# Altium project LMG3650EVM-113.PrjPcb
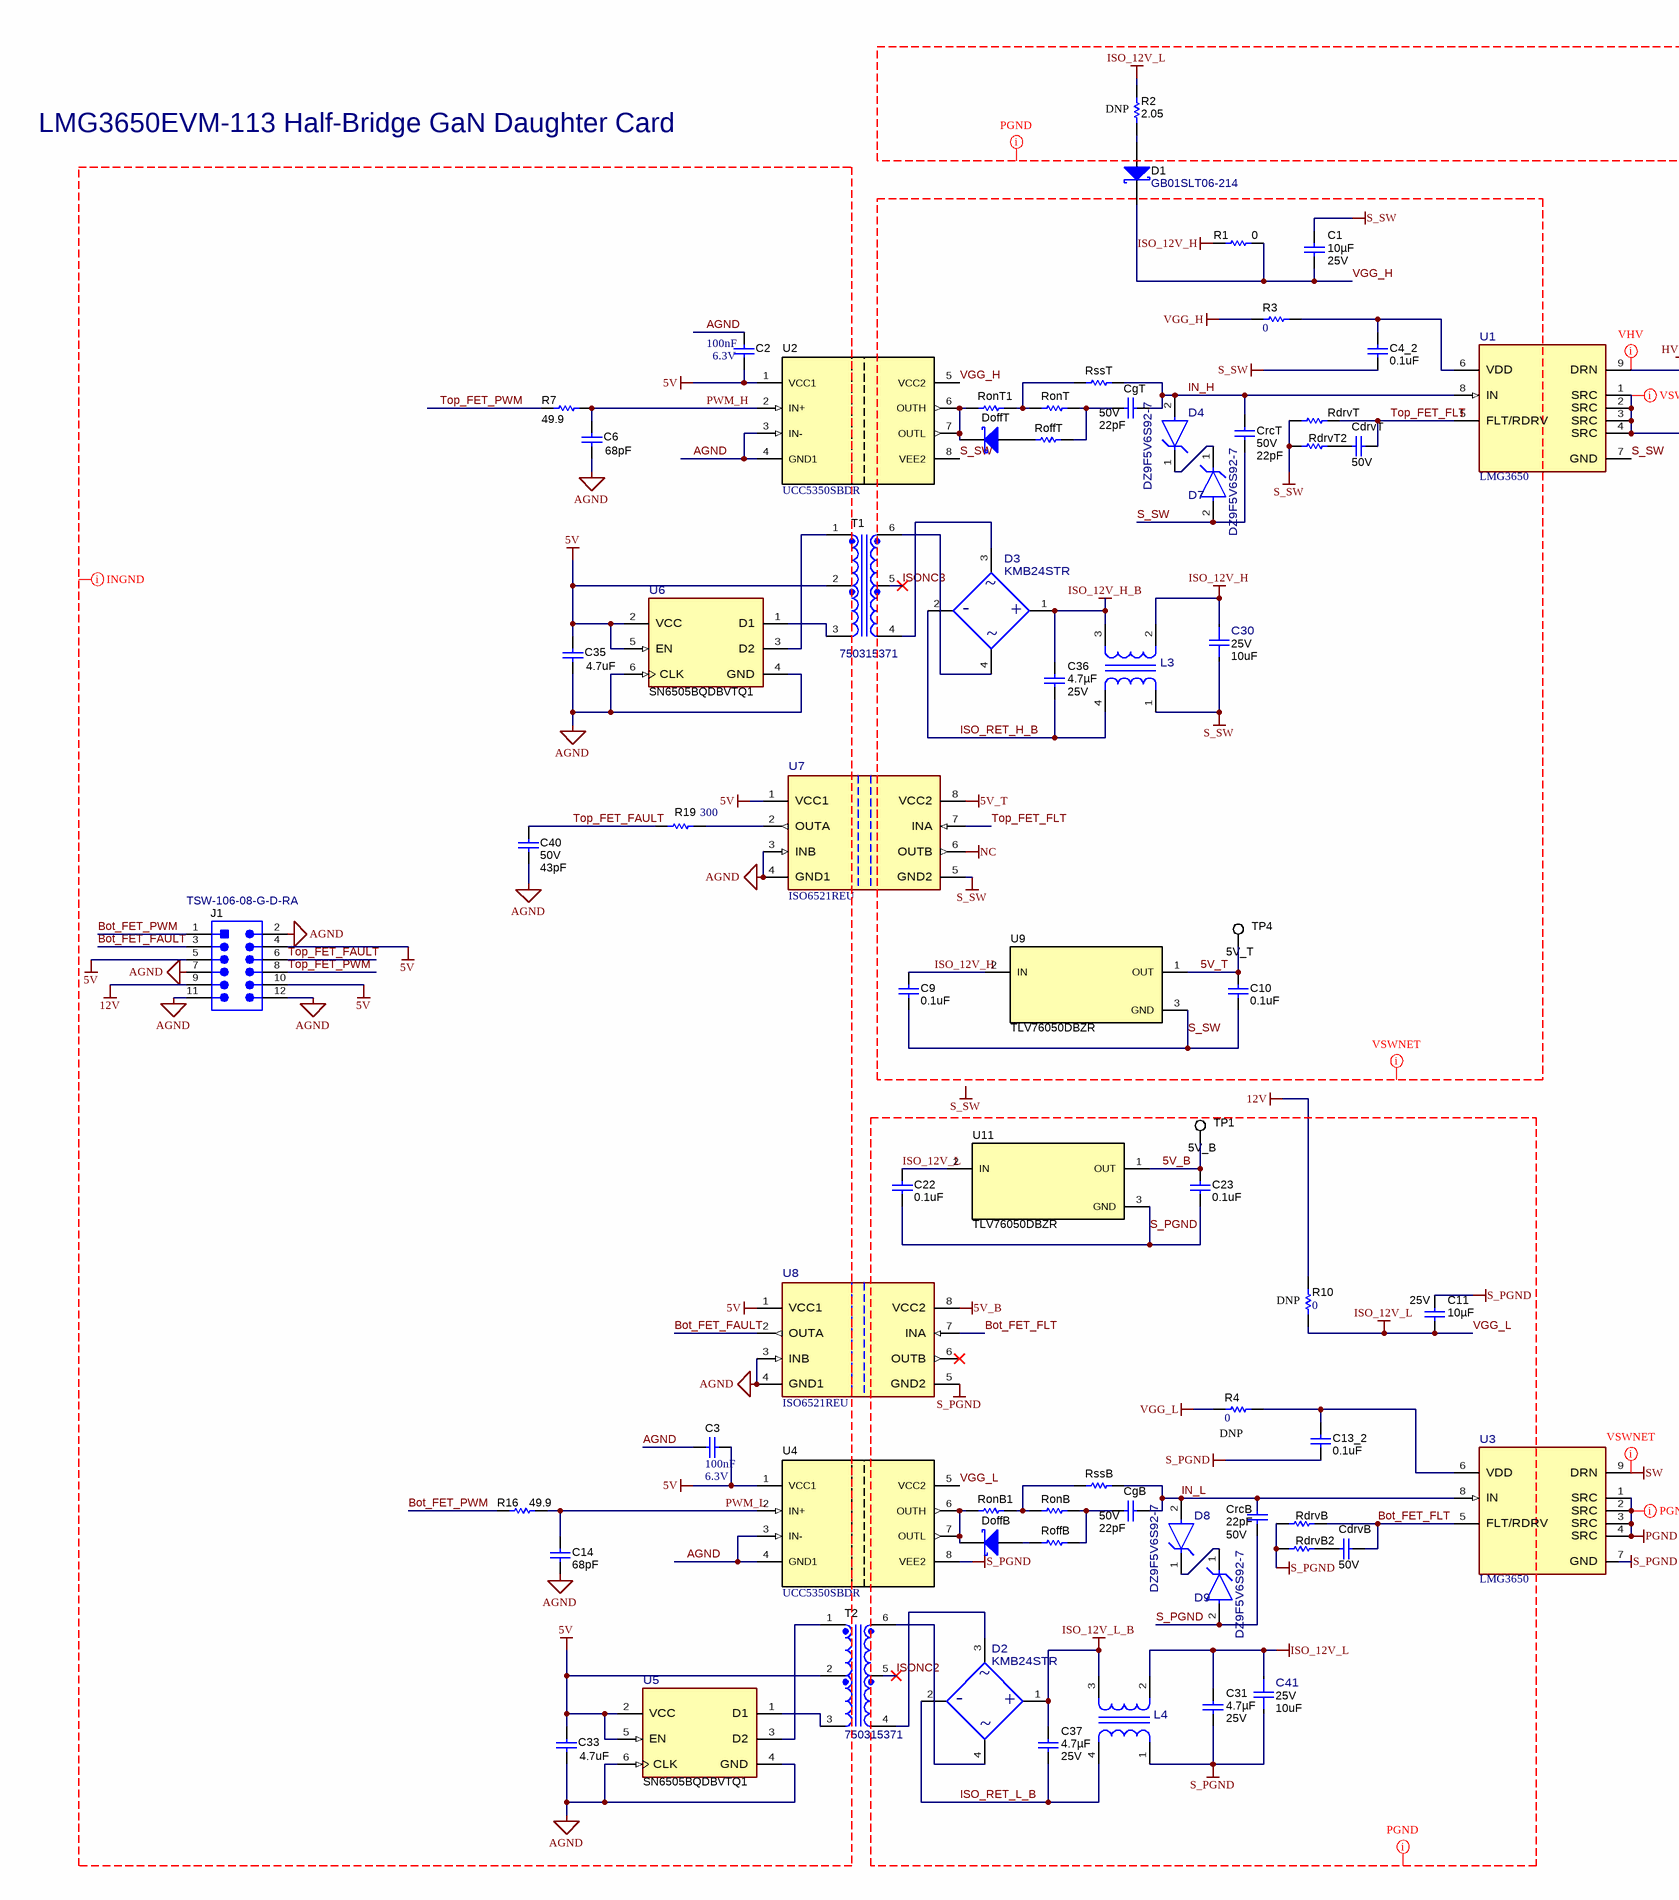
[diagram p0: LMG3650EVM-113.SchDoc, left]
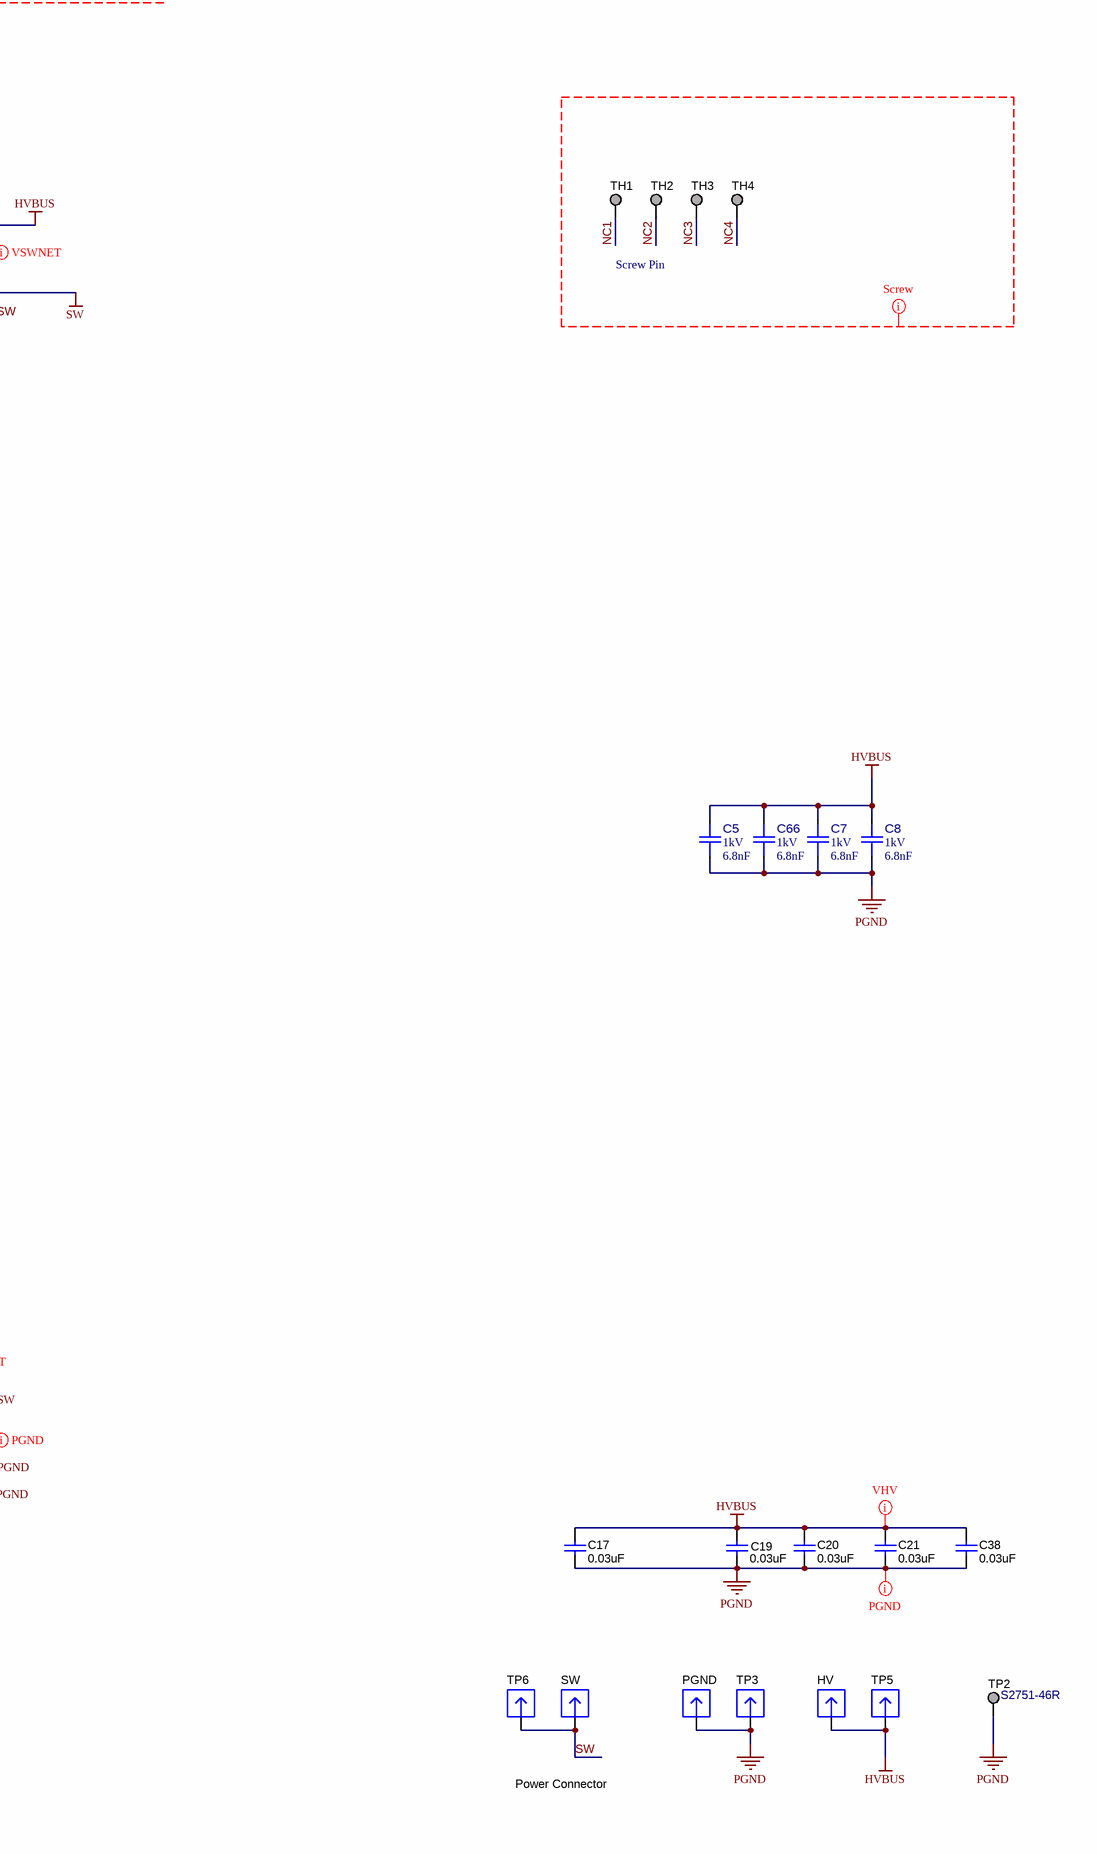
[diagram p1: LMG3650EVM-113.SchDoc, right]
CopyrightYear: 2020; Drawnby: Kyle Wolf; PCB_Layout: Kyle Wolf; PCB_Rev: A1; PRJ_Customer: Public Release; PRJ_Engineer: Kyle Wolf; PRJ_Number: HVP113; PRJ_Title: Sunliner; SCH_Rev: A1; TechSupport: http://www.ti.com/support; TID: N/A
2 sheets, 108 parts. Net scope: global (net labels, ports and power ports of the same name join across sheets).
Board file: LMG3650EVM-113.PcbDoc
Sheets:
  LMG3650EVM-113.SchDoc
  LMG3650EVM-113_Hardware.SchDoc

## Sheet LMG3650EVM-113.SchDoc: Phase Leg
size A2; Date: Not shown in title block; ApprovedBy: Not shown in title block; CheckedBy: Not shown in title block; Author: Not shown in title block; CompanyName: Not shown in title block; DrawnBy: Fei Yang; Engineer: Not shown in title block; Organization: Not shown in title block; Address1: Not shown in title block; Address2: Not shown in title block; Address3: Not shown in title block; Address4: Not shown in title block; DocumentNumber: 2; Revision: Use project parameter SCH_Rev; SheetNumber: 2; SheetTotal: 3; PageSetup: Record=PageOptions¦CenterHorizontal=True¦CenterVertical=True¦PrintScale=1.00¦XCorrection=1.00¦YCorrection=1.00¦PrintKind=0¦BorderSize=5000000¦LeftOffset=0¦BottomOffset=0¦Orientation=2¦PaperLength=1000¦PaperWidth=1000¦Scale=100¦PaperSource=15¦PrintQuality=600¦MediaType=1¦DitherType=10¦PaperKind=Letter¦PrintScaleMode=1

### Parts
C1  VDC_V: 25V  ValueDisplayed: 10µF  [1206_180]  (hidden comment: TMK316AB7106KLHT)
C2  Cap_F: 100nF  VDC_V: 6.3V  [0603]  (hidden comment: GRM188R70J104KA01D)
C3  Cap_F: 100nF  VDC_V: 6.3V  [0603]  (hidden comment: GRM188R70J104KA01D)
C4_2  ValueDisplayed: 0.1uF  [0402]  (hidden comment: C1005X7R1H104K050BB)
C5  VDC_V: 1kV  ValueDisplayed: 6.8nF  [FP-CGA6M1C0G3A682J200AE_1210-MFG]  (hidden comment: CGA6M1C0G3A682J200AE)
C6  ValueDisplayed: 68pF  [0402]  (hidden comment: C1005C0G1H680J050BA)
C7  VDC_V: 1kV  ValueDisplayed: 6.8nF  [FP-CGA6M1C0G3A682J200AE_1210-MFG]  (hidden comment: CGA6M1C0G3A682J200AE)
C8  VDC_V: 1kV  ValueDisplayed: 6.8nF  [FP-CGA6M1C0G3A682J200AE_1210-MFG]  (hidden comment: CGA6M1C0G3A682J200AE)
C9  ValueDisplayed: 0.1uF  [0402]  (hidden comment: C1005X7R1H104K050BB)
C10  ValueDisplayed: 0.1uF  [0402]  (hidden comment: C1005X7R1H104K050BB)
C11  VDC_V: 25V  ValueDisplayed: 10µF  [1206_180]  (hidden comment: TMK316AB7106KLHT)
C13_2  ValueDisplayed: 0.1uF  [0402]  (hidden comment: C1005X7R1H104K050BB)
C14  ValueDisplayed: 68pF  [0402]  (hidden comment: C1005C0G1H680J050BA)
C17  ValueDisplayed: 0.03uF  [1812_254]  (hidden comment: C1812C303KDGLCAUTO)
C19  ValueDisplayed: 0.03uF  [1812_254]  (hidden comment: C1812C303KDGLCAUTO)
C20  ValueDisplayed: 0.03uF  [1812_254]  (hidden comment: C1812C303KDGLCAUTO)
C21  ValueDisplayed: 0.03uF  [1812_254]  (hidden comment: C1812C303KDGLCAUTO)
C22  ValueDisplayed: 0.1uF  [0402]  (hidden comment: C1005X7R1H104K050BB)
C23  ValueDisplayed: 0.1uF  [0402]  (hidden comment: C1005X7R1H104K050BB)
C30  VDC_V: 25V  ValueDisplayed: 10uF  [FP-CGA4J1X7S1E106K125AC_0805-MFG]  (hidden comment: CGA4J1X7S1E106K125AC)
C31  ValueDisplayed: 4.7µF  VDC_V: 25V  [0603]  (hidden comment: GRT188C81E475KE13D)
C33  ValueDisplayed: 4.7uF  [0805_HV]  (hidden comment: GCM21BR71C475KA73L)
C35  ValueDisplayed: 4.7uF  [0805_HV]  (hidden comment: GCM21BR71C475KA73L)
C36  ValueDisplayed: 4.7µF  VDC_V: 25V  [0603]  (hidden comment: GRT188C81E475KE13D)
C37  ValueDisplayed: 4.7µF  VDC_V: 25V  [0603]  (hidden comment: GRT188C81E475KE13D)
C38  ValueDisplayed: 0.03uF  [1812_254]  (hidden comment: C1812C303KDGLCAUTO)
C40  VDC_V: 50V  ValueDisplayed: 43pF  [0402]  (hidden comment: GCQ1555C1H430JB01D)
C41  VDC_V: 25V  ValueDisplayed: 10uF  [FP-CGA4J1X7S1E106K125AC_0805-MFG]  (hidden comment: CGA4J1X7S1E106K125AC)
C66  VDC_V: 1kV  ValueDisplayed: 6.8nF  [FP-CGA6M1C0G3A682J200AE_1210-MFG]  (hidden comment: CGA6M1C0G3A682J200AE)
CdrvB  VDC_V: 50V  [0402]  (hidden comment: GCM1555C1H220JA16D)
CdrvT  VDC_V: 50V  [0402]  (hidden comment: GCM1555C1H220JA16D)
CgB  VDC_V: 50V  ValueDisplayed: 22pF  [0402]  (hidden comment: GCM1555C1H220JA16D (NC))
CgT  VDC_V: 50V  ValueDisplayed: 22pF  [0402]  (hidden comment: GCM1555C1H220JA16D (NC))
CrcB  VDC_V: 50V  ValueDisplayed: 22pF  [0402]  (hidden comment: GCM1555C1H220JA16D)
CrcT  VDC_V: 50V  ValueDisplayed: 22pF  [0402]  (hidden comment: GCM1555C1H220JA16D)
D1  GB01SLT06-214  [SMB]
D2  KMB24STR  [FP-KMB24STR_SMD4-MFG]
D3  KMB24STR  [FP-KMB24STR_SMD4-MFG]
D4  DZ9F5V6S92-7  [FP-CDZVT2R5.1B_SOD-923-MFG]
D7  DZ9F5V6S92-7  [FP-CDZVT2R5.1B_SOD-923-MFG]
D8  DZ9F5V6S92-7  [FP-CDZVT2R5.1B_SOD-923-MFG]
D9  DZ9F5V6S92-7  [FP-CDZVT2R5.1B_SOD-923-MFG]
DoffB  NSR05F30NXT5G  [DSN2_0402]  (value not drawn)
DoffT  NSR05F30NXT5G  [DSN2_0402]  (value not drawn)
HV  3621-0-32-15-00-00-08-0  [Mill-Max_3621-0-32-xx-00-00-08-0]  (value not drawn)
J1  TSW-106-08-G-D-RA  [AB12-DEST]
L3  ACM2012-900-2P-T001  [FP-ACM2012-900-2P-T001_SMD4-MFG]  (value not drawn)
L4  ACM2012-900-2P-T001  [FP-ACM2012-900-2P-T001_SMD4-MFG]  (value not drawn)
PGND  3621-0-32-15-00-00-08-0  [Mill-Max_3621-0-32-xx-00-00-08-0]  (value not drawn)
R1  ValueDisplayed: 0  [0805_HV]  (hidden comment: CRCW08050000Z0EAHP)
R2  ValueDisplayed: 2.05  [1206]  (hidden comment: CRCW12062R05FKEA)  (no BOM)
R3  ValueDisplayed: 0  [0603]  (hidden comment: CRCW06030000Z0EA)
R4  ValueDisplayed: 0  [0603]  (hidden comment: CRCW06030000Z0EA)
R7  ValueDisplayed: 49.9  [0402]  (hidden comment: CRCW040249R9FKED)
R10  ValueDisplayed: 0  [1206]  (hidden comment: ERJ-8GEY0R00V)  (no BOM)
R16  ValueDisplayed: 49.9  [0402]  (hidden comment: CRCW040249R9FKED)
R19  ValueDisplayed: 300  [0402]  (hidden comment: CRCW0402300RJNED)
RdrvB  ERJ-2GEJ203X  [0402]  (value not drawn)
RdrvB2  ERJ-2GEJ203X  [0402]  (value not drawn)
RdrvT  ERJ-2GEJ203X  [0402]  (value not drawn)
RdrvT2  ERJ-2GEJ203X  [0402]  (value not drawn)
RoffB  CRCW04022R40JNED  [0402]  (value not drawn)
RoffT  CRCW04022R40JNED  [0402]  (value not drawn)
RonB  CRCW04029R10JNED  [0402]  (value not drawn)
RonB1  CRCW04029R10JNED  [0402]  (value not drawn)
RonT  CRCW04029R10JNED  [0402]  (value not drawn)
RonT1  CRCW04029R10JNED  [0402]  (value not drawn)
RssB  CRCW04029R10JNED  [0402]  (value not drawn)
RssT  CRCW04029R10JNED  [0402]  (value not drawn)
SW  3621-0-32-15-00-00-08-0  [Mill-Max_3621-0-32-xx-00-00-08-0]  (value not drawn)
T1  750315371  [Wurth_750315371]
T2  750315371  [Wurth_750315371]
TH1  (no value)  [TP_H045P075]  (no BOM)
TH2  (no value)  [TP_H045P075]  (no BOM)
TH3  (no value)  [TP_H045P075]  (no BOM)
TH4  (no value)  [TP_H045P075]  (no BOM)
TP1  5V_B  [Via_TP]  (no BOM)
TP2  S2751-46R  [Harwin_S2751-46R]
TP3  3621-0-32-15-00-00-08-0  [Mill-Max_3621-0-32-xx-00-00-08-0]  (value not drawn)
TP4  5V_T  [Via_TP]  (no BOM)
TP5  3621-0-32-15-00-00-08-0  [Mill-Max_3621-0-32-xx-00-00-08-0]  (value not drawn)
TP6  3621-0-32-15-00-00-08-0  [Mill-Max_3621-0-32-xx-00-00-08-0]  (value not drawn)
U1  LMG3650  [KLA0009A-NV]
U2  UCC5350SBDR  [D0008B_HV]
U3  LMG3650  [KLA0009A-NV]
U4  UCC5350SBDR  [D0008B_HV]
U5  SN6505BQDBVTQ1  [DBV0006A-MFG]
U6  SN6505BQDBVTQ1  [DBV0006A-MFG]
U7  ISO6521REU  [REU0008A-MFG]
U8  ISO6521REU  [REU0008A-MFG]
U9  TLV76050DBZR  [DBZ0003A_N]
U11  TLV76050DBZR  [DBZ0003A_N]

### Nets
5V: C2.1 C3.1 C33.1 C35.1 J1.4 J1.5 J1.10 T1.2 T2.2 U2.1(VCC1) U4.1(VCC1) U5.2(VCC) U5.5(EN) U6.2(VCC) U6.5(EN) U7.1(VCC1) U8.1(VCC1)
5V_B: C23.1 TP1.1 U8.8(VCC2) U11.1(OUT)
5V_T: C10.1 TP4.1 U7.8(VCC2) U9.1(OUT)
12V: J1.9 R10.1
AGND: C2.2 C3.2 C6.2 C14.1 C33.2 C35.2 C40.2 J1.2 J1.7 J1.11 J1.12 U2.3(IN-) U2.4(GND1) U4.3(IN-) U4.4(GND1) U5.4(GND) U5.6(CLK) U6.4(GND) U6.6(CLK) U7.3(INB) U7.4(GND1) U8.3(INB) U8.4(GND1)
HVBUS: C5.2 C7.2 C8.2 C17.1 C19.1 C20.1 C21.1 C38.1 C66.2 HV.1 TP5.1 U1.9(DRN)
ISO_12V_H: C9.1 C30.1 L3.2 R1.1 U9.2(IN)
ISO_12V_H_B: C36.1 D3.1(-) L3.3
ISO_12V_L: C11.2 C22.1 C31.1 C41.1 L4.2 R2.1 R4.1 R10.2 U4.5(VCC2) U11.2(IN)  [also labelled VGG_L]
ISO_12V_L_B: C37.1 D2.1(-) L4.3
NC: U7.6(OUTB)
PGND: C5.1 C7.1 C8.1 C17.2 C19.2 C20.2 C21.2 C38.2 C66.1 PGND.1 TP2.1 TP3.1 U3.1(SRC) U3.2(SRC) U3.3(SRC) U3.4(SRC)
S_PGND: C11.1 C13_2.2 C22.2 C23.2 C31.2 C41.2 CrcB.1 D9.2(Anode) L4.1 RdrvB.1 RdrvB2.1 U3.7(GND) U4.8(VEE2) U8.5(GND2) U11.3(GND)
S_SW: C1.2 C4_2.2 C9.2 C10.2 C30.2 CrcT.1 D7.2(Anode) L3.1 RdrvT.1 RdrvT2.1 U1.7(GND) U2.8(VEE2) U7.5(GND2) U9.3(GND)
SW: SW.1 TP6.1 U1.1(SRC) U1.2(SRC) U1.3(SRC) U1.4(SRC) U3.9(DRN)
VGG_H: C1.1 D1.1(K) R1.2 R3.1 U2.5(VCC2)
Bot_FET_FAULT: J1.3 U8.2(OUTA)
Bot_FET_FLT: CdrvB.2 RdrvB.2 U3.5(FLT/RDRV) U8.7(INA)
Bot_FET_PWM: J1.1 R16.1
IN_H: CgT.2 CrcT.2 D4.2(Anode) RssT.2 U1.8(IN)
IN_L: CgB.2 CrcB.2 D8.2(Anode) RssB.2 U3.8(IN)
ISO_RET_H_B: C36.2 D3.2(+) L3.4
ISO_RET_L_B: C37.2 D2.2(+) L4.4
ISONC2: T2.5
ISONC3: T1.5
NC1: TH1.1
NC2: TH2.1
NC3: TH3.1
NC4: TH4.1
PWM_H: C6.1 R7.2 U2.2(IN+)
PWM_L: C14.2 R16.2 U4.2(IN+)
Top_FET_FAULT: C40.1 J1.6 R19.2
Top_FET_FLT: CdrvT.2 RdrvT.2 U1.5(FLT/RDRV) U7.7(INA)
Top_FET_PWM: J1.8 R7.1
NetC4_2_1: C4_2.1 R3.2 U1.6(VDD)
NetC13_2_1: C13_2.1 R4.2 U3.6(VDD)
NetCdrvB_1: CdrvB.1 RdrvB2.2
NetCdrvT_1: CdrvT.1 RdrvT2.2
NetCgB_1: CgB.1 RoffB.2 RonB.2
NetCgT_1: CgT.1 RoffT.2 RonT.2
NetD1_2: D1.2(A) R2.2
NetD2_3: D2.3(1_~) T2.4
NetD2_4: D2.4(2_~) T2.6
NetD3_3: D3.3(1_~) T1.4
NetD3_4: D3.4(2_~) T1.6
NetD4_1: D4.1(Cathode) D7.1(Cathode)
NetD8_1: D8.1(Cathode) D9.1(Cathode)
NetDoffB_1: DoffB.1(K) RonB1.1 U4.6(OUTH) U4.7(OUTL)
NetDoffB_2: DoffB.2(A) RoffB.1
NetDoffT_1: DoffT.1(K) RonT1.1 U2.6(OUTH) U2.7(OUTL)
NetDoffT_2: DoffT.2(A) RoffT.1
NetR19_1: R19.1 U7.2(OUTA)
NetRonB_1: RonB.1 RonB1.2 RssB.1
NetRonT_1: RonT.1 RonT1.2 RssT.1
NetT1_1: T1.1 U6.3(D2)
NetT1_3: T1.3 U6.1(D1)
NetT2_1: T2.1 U5.3(D2)
NetT2_3: T2.3 U5.1(D1)

Not connected (* = marked no-connect by the designer): U8 6(OUTB)*

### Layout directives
net class VSWNET: 5V_T, IN_H, ISO_12V_H, ISO_12V_H_B, ISO_RET_H_B, ISONC3, NC, S_SW, SW, Top_FET_FLT, VGG_H
net class INGND: 5V, 12V, AGND, Bot_FET_FAULT, Bot_FET_PWM, PWM_H, PWM_L, Top_FET_FAULT, Top_FET_PWM
net class PGND: 5V_B, Bot_FET_FLT, IN_L, ISO_12V_L, ISO_12V_L_B, ISO_RET_L_B, ISONC2, PGND, S_PGND, VGG_L
net class Screw: NC1, NC2, NC3, NC4
net class VHV: HVBUS

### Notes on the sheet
- LMG3650EVM-113 Half-Bridge GaN Daughter Card
- (near R2) DNP
- Screw Pin
- (near R10) DNP
- (near R4) DNP
- Power Connector
- Labels drawn without touching a wire or pin: S_SW

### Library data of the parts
C1 C11 = CMP-0750154-1: CAP, CERM, 10 µF, 25 V,+/- 10%, X7R, AEC-Q200 Grade 1, 1206; Manufacturer: Taiyo Yuden; AEC Qualified: Y; SizeZ_mm: 1.8; TaMax_C: 125°C; TaMin_C: -55°C; Cap_Case: 1206; Polarized: N; AEC Grade: 1; SizeY_mm: 1.6; Value: 10uF; SizeX_mm: 3.2; SizeAreaWB_mm2: 10.92; AEC Category: Q200; U/M: EA; SizeArea_mm2: 5.12
C2 C3 = CMP-0007359-4: CAP, CERM, 0.1 uF, 6.3 V, +/- 10%, X7R, 0603; Manufacturer: MuRata; TaMin_C: -55°C; Polarized: N; SizeAreaWB_mm2: 4.68; Value1: Unknown; U/M: EA; Value: 0.1uF; TaMax_C: 125°C; SizeZ_mm: 1; SizeX_mm: 1.6; SizeY_mm: 0.8; SizeArea_mm2: 1.28; AEC Category: Q200
C4_2 C9 C10 C13_2 C22 C23 = CMP-0006297-2: CAP, CERM, 0.1 uF, 50 V, +/- 10%, X7R, 0402; Manufacturer: TDK; Polarized: N; Value: 0.1uF; U/M: EA; Cap_F: 100nF; ESR_ohm: 0.039064; Value1: 0.039064 ohm; VDC_V: 50V; IRMS_A: 8.14669dA; TaMin_C: -55°C; TaMax_C: 125°C; AEC Category: Q200; SizeArea_mm2: 0.5; SizeAreaWB_mm2: 3; SizeX_mm: 1; SizeZ_mm: 0.6
C5 C7 C8 C66 = CMP-0092736-1: Cap Ceramic 6.8nF 1000V C0G 5% Pad SMD 1210 +125°C Automotive T/R; Manufacturer: TDK; Tolerance_%: 0.05%; AEC Qualified: Yes; SizeZ_mm: 2.8mm; AEC Grade: Grade 1; TempCo: 30ppm/°C
C6 C14 = CMP-0006251-2: CAP, CERM, 68 pF, 50 V, +/- 5%, C0G/NP0, 0402; Manufacturer: TDK; Alternate Manufacturer: Murata; Alternate PartNumber: GRM1555C1H680JA01D; TaMin_C: -55°C; Polarized: N; SizeAreaWB_mm2: 3; Value1: Unknown; U/M: EA; Value: 68pF; TaMax_C: 125°C; SizeZ_mm: 0.6; SizeX_mm: 1; SizeY_mm: 0.5; Value2: 50V; AEC Category: Q200
C17 C19-C21 C38 = CMP-0009326-2: 0.03 µF ±10% 1000V (1kV) Ceramic Capacitor C0G, NP0 1812 (4532 Metric); Manufacturer: Kemet; Polarized: N; Value: 0.03uF; U/M: EA; Cap_F: 30nF; Value1: Unknown; TaMin_C: -55°C; TaMax_C: 125°C; Cap_Case: 1812; AEC Category: Q200; SizeArea_mm2: 14.4; SizeAreaWB_mm2: 23.1; SizeX_mm: 4.5; SizeY_mm: 3.2; SizeZ_mm: 2.54
C30 C41 = CMP-0091069-1: Cap Ceramic 10uF 25V X7S 10% Pad SMD 0805 +125°C Automotive T/R; Manufacturer: TDK Corporation; AEC Qualified: Yes; AEC Grade: Grade 1; Value: 10µF; Tolerance_%: 0.1%; SizeZ_mm: 1.45mm; TempCo: 22%
C31 C36 C37 = CMP-0085645-1: CAP, CERM, 4.7 µF, 25 V,+/- 10%, X6S, AEC-Q200 Grade 2, 0603; Manufacturer: MuRata; TaMax_C: 105°C; SizeY_mm: 0.8; AEC Grade: 2; Polarized: N; SizeZ_mm: 1; SizeArea_mm2: 1.28; U/M: EA; SizeAreaWB_mm2: 4.68; SizeX_mm: 1.6; TaMin_C: -55°C; AEC Qualified: Y; AEC Category: Q200; Value: 4.7uF
C33 C35 = CMP-0008020-2: CAP, CERM, 4.7 uF, 16 V, +/- 10%, X7R, AEC-Q200 Grade 1, 0805; Manufacturer: MuRata; TaMin_C: -55°C; Polarized: N; SizeAreaWB_mm2: 6.75; Value1: Unknown; U/M: EA; Value: 4.7uF; TaMax_C: 125°C; SizeZ_mm: 1.45; SizeX_mm: 2; SizeY_mm: 1.25; Cap_Case: 0805; Value2: 16V; SizeArea_mm2: 2.5; AEC Qualified: Y; Cap_F: 4.7µF; AEC Grade: 1; AEC Category: Q200
C40 = CMP-0860835-1: CAP, CERM, 43 pF, 50 V,+/- 5%, C0G/NP0, AEC-Q200 Grade 1, 0402; Manufacturer: MuRata; SizeY_mm: 0.5; SizeZ_mm: 0.6; AEC Qualified: Y; AEC Grade: 1; AEC Category: Q200; U/M: EA; Value: 43pF; Polarized: N; TaMin_C: -55°C; SizeAreaWB_mm2: 3; TaMax_C: 125°C
CdrvB CdrvT CgB CgT CrcB CrcT = CMP-0006348-2: CAP, CERM, 22 pF, 50 V, +/- 5%, C0G/NP0, AEC-Q200 Grade 1, 0402; Manufacturer: MuRata; TaMin_C: -55°C; Polarized: N; SizeAreaWB_mm2: 3; Value1: Unknown; U/M: EA; Value: 22pF; TaMax_C: 125°C; SizeZ_mm: 0.6; SizeX_mm: 1; SizeY_mm: 0.5; AEC Qualified: Y; AEC Category: Q200
D1 = CMP-0076998-2: Diode, Schottky, 650 V, 1 A, SMB; Manufacturer: GeneSiC Semiconductor; Value1: 1A; SizeZ_mm: 2.6; Value: 650V; SizeAreaWB_mm2: 44.156; TJmax_C: 175°C; RJC_CperW: 3.55; SizeArea_mm2: 21.336; AEC Category: Q101; Value2: 2V; SizeY_mm: 3.81; SizeX_mm: 5.6
D2 D3 = CMP-0090590-2: Bridge Rectifier Single Phase Schottky 40V Surface Mount MBS; Manufacturer: SMC Diode Solutions; Max Surge Forward Current: 50A; AEC Qualified: No; Cap_F: 28pF; AEC Category: Q101; Peak Reverse Current: 0.1mA; SizeZ_mm: 2.7mm; Standoff Height: 0.2mm; CompType: Diode; TJmax_C: 150°C; Forward Current: 2A
D4 D7-D9 = CMP-0123139-1: DIODE ZENER 5.6V 200MW SOD923; Manufacturer: ROHM; Part Number: CDZVT2R5.1B; AEC Qualified: No; SizeZ_mm: 0.4mm; TJmax_C: 150°C; Vf_V: 5.2V; Vr_V: 1.5V; Max Reverse Leakage Current: 2uA; Power_W: 100mW; Vz_V: 5.1V; Zener Impedance: 80Ω
DoffB DoffT = CMP-0077002-2: Diode, Schottky, 30 V, 0.5 A, 0402 Diode; Manufacturer: ON Semiconductor; Green_REACh: Passed; Value: 30V; AEC Category: Q101; Io_A: 500mA; Vf_V: 430mV; SizeZ_mm: 0.31; SizeAreaWB_mm2: 3.2; TJmax_C: 150°C; Green_Lifecycle: Active; Value2: 0.43V; SizeX_mm: 1.0; SizeY_mm: 0.6; Value1: 0.5A
HV PGND SW TP3 TP5 TP6 = CMP-0082316-1: Manufacturer: Mill-Max; CompType: PCB Pin; ContactFinish: Gold; Gender: Male; Row_Count: 1
J1 = CMP-0075414-2: Header, 100mil, 6x2, Gold, R/A, TH; Manufacturer: Samtec; Pitch_mm: 2.54; Cert_VDE: N; Gender: Male; Cert_CSA: Y; Current_A: 6.3A; Voltage_V: 550V; Row_Count: 2
L3 L4 = CMP-0090488-1: 2 Line Common Mode Choke Surface Mount 90 Ohms @ 100MHz 400mA DCR 190mOhm; Manufacturer: TDK; SizeZ_mm: 1.3mm; DCR_ohm: 0.19; AEC Qualified: Yes; AEC Grade: Grade 2; Impedance At Frequency: 90Ω @ 100MHz
R1 = CMP-0020443-3: RES, 0, 5%, 0.333 W, AEC-Q200 Grade 0, 0805; Manufacturer: Vishay-Dale; Power_W: 333mW; TempCo: 200 ppm/C; Value_Code: 0000; Value: 0; EIA_Code: E24; SizeX_mm: 2; SizeY_mm: 1.25; SizeZ_mm: 1.45; Value2: 0.333W; SizeArea_mm2: 2.5; AEC Qualified: Y; AEC Category: Q200; VDC_V: 150V
R2 = CMP-0016879-3: RES, 2.05, 1%, 0.25 W, AEC-Q200 Grade 0, 1206; Manufacturer: Vishay-Dale; Power_W: 250mW; TempCo: 100 ppm/C; Value_Code: 2R05; Value: 2.05; EIA_Code: E96; SizeX_mm: 3.2; SizeY_mm: 1.6; SizeZ_mm: 1.35; Value2: 0.25W; SizeArea_mm2: 5.12; AEC Qualified: Y; VDC_V: 200V; AEC Category: Q200; AEC Grade: 0
R3 R4 = CMP-0025697-4: RES, 0, 5%, 0.1 W, AEC-Q200 Grade 0, 0603; Manufacturer: Vishay-Dale; Power_W: 100mW; TempCo: 200 ppm/C; Value_Code: 0000; Value: 0; EIA_Code: E24; SizeX_mm: 1.6; SizeY_mm: 0.8; SizeZ_mm: 1; Value2: 0.1W; SizeArea_mm2: 1.28; AEC Qualified: Y; VDC_V: 75V; AEC Category: Q200
R7 R16 = CMP-0026404-2: RES, 49.9, 1%, 0.063 W, AEC-Q200 Grade 0, 0402; Manufacturer: Vishay-Dale; Power_W: 63mW; TempCo: 100 ppm/C; Value_Code: 49R9; Value: 49.9; EIA_Code: E96; SizeX_mm: 1; SizeY_mm: 0.5; SizeZ_mm: 0.6; Value2: 0.063W; AEC Qualified: Y; VDC_V: 50V; AEC Category: Q200; AEC Grade: 0
R10 = CMP-0018748-3: RES, 0, 5%, 0.25 W, AEC-Q200 Grade 0, 1206; Manufacturer: Panasonic; Power_W: 250mW; TempCo: 600 ppm/C; Value_Code: 0000; Value: 0; EIA_Code: E24; SizeX_mm: 3.2; SizeY_mm: 1.6; SizeZ_mm: 1.35; Value2: 0.25W; SizeArea_mm2: 5.12; AEC Qualified: Y; VDC_V: 200V; AEC Category: Q200; SizeAreaWB_mm2: 10.92
R19 = CMP-0026902-3: RES, 300, 5%, 0.063 W, AEC-Q200 Grade 0, 0402; Manufacturer: Vishay-Dale; Power_W: 63mW; TempCo: 200 ppm/C; Value_Code: 300R; Value: 300; EIA_Code: E24; SizeX_mm: 1; SizeY_mm: 0.5; SizeZ_mm: 0.6; Value2: 0.063W; AEC Qualified: Y; VDC_V: 50V; AEC Category: Q200; AEC Grade: 0
RdrvB RdrvB2 RdrvT RdrvT2 = CMP-0026996-1: RES, 20 k, 5%, 0.1 W, AEC-Q200 Grade 0, 0402; Manufacturer: Panasonic; Power_W: 100mW; TempCo: 200 ppm/C; Value_Code: 20k0; U/M: EA; Value: 20k; EIA_Code: E24; SizeX_mm: 1; SizeY_mm: 0.5; SizeZ_mm: 0.6; Value2: 0.1W; AEC Qualified: Y; VDC_V: 50V; AEC Grade: 0; AEC Category: Q200
RoffB RoffT = CMP-0026899-2: RES, 2.4, 5%, 0.063 W, 0402; Manufacturer: Vishay-Dale; Power_W: 63mW; TempCo: 200 ppm/C; Value_Code: 2R40; U/M: EA; Value: 2.4; EIA_Code: E24; SizeX_mm: 1; SizeY_mm: 0.5; SizeZ_mm: 0.6; Value2: 0.063W; VDC_V: 50V; AEC Category: Q200
RonB RonB1 RonT RonT1 RssB RssT = CMP-0026991-4: RES, 9.1, 5%, 0.063 W, AEC-Q200 Grade 0, 0402; Manufacturer: Vishay-Dale; SizeY_mm: 0.5; Value: 9.1; Power_W: 63mW; VDC_V: 50V; TempCo: 200 ppm/C; EIA_Code: E24; Value2: 0.063W; AEC Category: Q200; AEC Grade: 0; SizeZ_mm: 0.6; SizeX_mm: 1; Value_Code: 9R10; AEC Qualified: Y
T1 T2 = CMP-0030623-1: Transformer, 105uH, TH; Manufacturer: Wurth Elektronik; Green_Lifecycle: Active; DCR_ohm: 0.06; Green_REACh: Passed; Lp: 105; Ns1toNp: 1.1; Ind_H: 105µH
TH1-TH4 = CMP-0003719-1: Testpoint; Manufacturer: Texas Instruments; Key: TP_H0.45P0.75; CompType: Pad
TP1 TP4 = CMP-0055144-1: Via Testpoint; CNHeader: FALSE; Green_Lifecycle: Active; Green_REACh: Passed; CT: TRUE
TP2 = CMP-0003968-1: Test Point, SMT; Manufacturer: Harwin
U1 U3 = CMP-0120607-2: Manufacturer: Texas Instruments; Part Number: LMG365x; SizeZ_mm: 2.35mm; AEC Qualified: No; Standoff Height: 0.1mm; AEC Category: Q200; CompType: IC
U2 U4 = CMP-0077706-1: 3-kVRMS Single-Channel Isolated Gate Drivers, D0008B (SOIC-8); Alternate Manufacturer: Texas Instruments; SizeAreaWB_mm2: 55.2; SizeZ_mm: 1.75; SizeX_mm: 6.0; SizeY_mm: 4.9; SizeArea_mm2: 29.4; CompType: IC; AEC Qualified: N; AEC Category: Q200
U5 U6 = CMP-0089033-2: Transformer Driver PMIC SOT-23-6; Manufacturer: Texas Instruments; CompType: IC; AEC Category: Q200; SizeZ_mm: 1.45mm; AEC Qualified: Yes
U7 U8 = CMP-0035039-1: General Purpose Dual-Channel Functional Isolators; Manufacturer: Texas Instruments; Interface: LVCMOS; Max Supply Voltage: 5.5V; Min Supply Voltage: 1.71V; Nominal Supply Current: 1.2-5.2mA; Standoff Height: 0mm; SizeZ_mm: 1.05mm; AEC Qualified: No; TaMax_C: +125°C; TaMin_C: -40°C; TJmax_C: +150°C
U9 U11 = CMP-0074892-1: 100-mA, 30-V, Fixed-Output, Linear-Voltage Regulator, DBZ0003A (SOT-23-3); Alternate PartNumber: TLV76050DBZT; Alternate Manufacturer: Texas Instruments; SizeAreaWB_mm2: 14.0; SizeZ_mm: 1.12; SizeX_mm: 2.5; SizeY_mm: 3.0; SizeArea_mm2: 7.5; CompType: IC; AEC Qualified: N; AEC Category: Q200

## Sheet LMG3650EVM-113_Hardware.SchDoc: Hardware
size 431 x 279 mm; Date: Not shown in title block; ApprovedBy: Not shown in title block; CheckedBy: Not shown in title block; Author: Not shown in title block; CompanyName: Not shown in title block; DrawnBy: Fei Yang; Engineer: Not shown in title block; Organization: Not shown in title block; Address1: Not shown in title block; Address2: Not shown in title block; Address3: Not shown in title block; Address4: Not shown in title block; DocumentNumber: 3; Revision: Use project parameter SCH_Rev; SheetNumber: 3; SheetTotal: 3; PageSetup: Record=PageOptions¦CenterHorizontal=True¦CenterVertical=True¦PrintScale=1.00¦XCorrection=1.00¦YCorrection=1.00¦PrintKind=0¦BorderSize=5000000¦LeftOffset=0¦BottomOffset=0¦Orientation=2¦PaperLength=1000¦PaperWidth=1000¦Scale=100¦PaperSource=15¦PrintQuality=600¦MediaType=1¦DitherType=10¦PaperKind=Letter¦PrintScaleMode=1
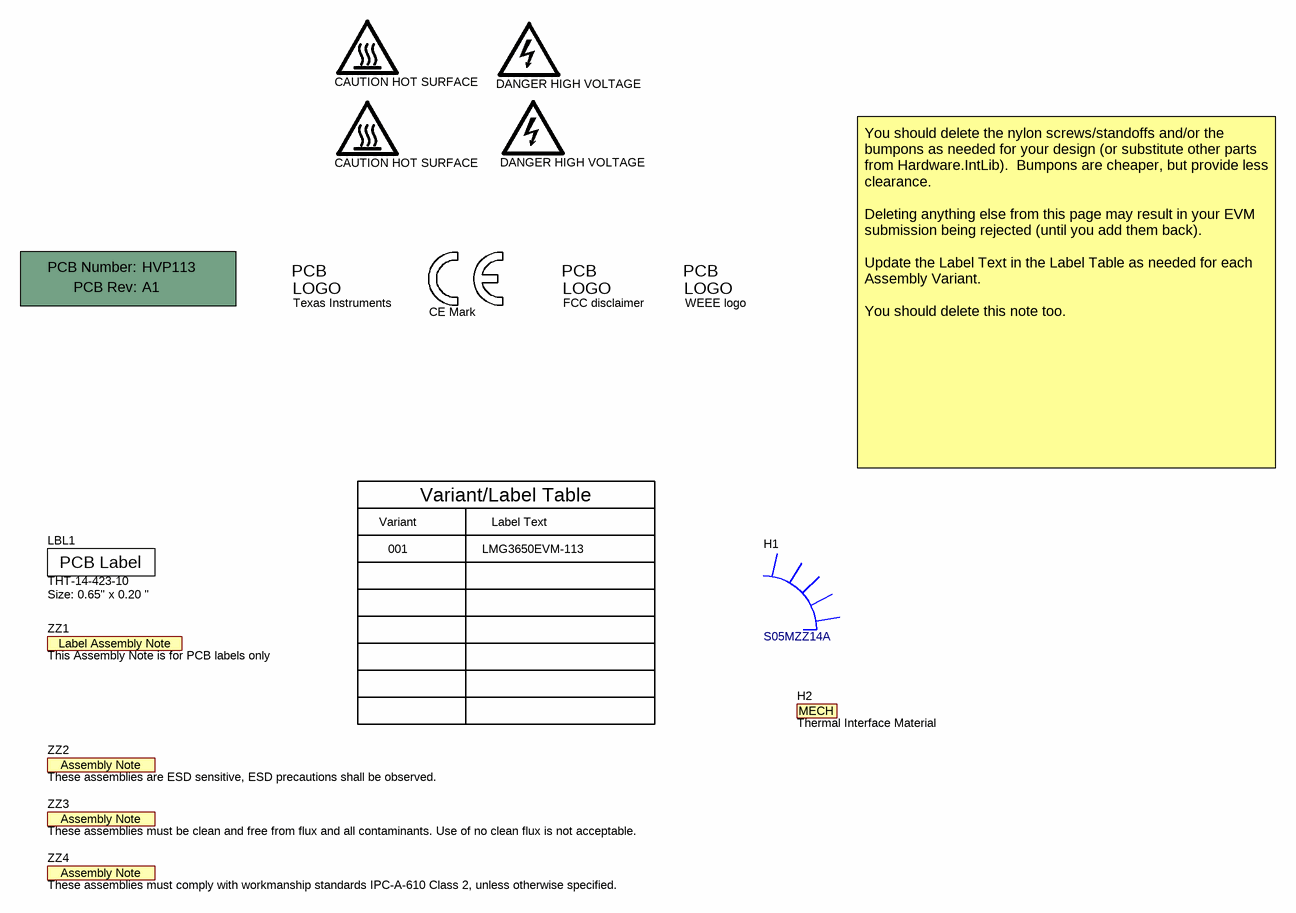
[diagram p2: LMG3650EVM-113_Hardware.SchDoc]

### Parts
!PCB  Printed Circuit Board  (value not drawn)  (mechanical)
H1  S05MZZ14A  [S05MZZ14]
H2  Thermal Interface Material  (mechanical)
LBL1  THT-14-423-10  Note: Size: 0.65" x 0.20 "  [Label_650x200]
LOGO1  CAUTION HOT SURFACE  [IEC_HotSurface_Small]  (no BOM)
LOGO2  DANGER HIGH VOLTAGE  [IEC_HighVoltage_Small]  (no BOM)
LOGO3  CAUTION HOT SURFACE  [IEC_HotSurface_Small]  (no BOM)
LOGO4  DANGER HIGH VOLTAGE  [IEC_HighVoltage_Small]  (no BOM)
Logo5  CE Mark  [CE_Mark_5mm]  (no BOM)
Logo6  Texas Instruments  [TI_Stacked_Overlay_Small]  (no BOM)
Logo7  FCC disclaimer  [FCC_disclaimer]  (no BOM)
Logo8  WEEE logo  [WEEE_Minimum]  (no BOM)
ZZ1  This Assembly Note is for PCB labels only  [AssemblyNoteLabel]  (no BOM)
ZZ2  These assemblies are ESD sensitive, ESD precautions shall be observed.  [AssemblyNote]  (no BOM)
ZZ3  These assemblies must be clean and free from flux and all contaminants. Use of no clean flux is not acceptable.  [AssemblyNote]  (no BOM)
ZZ4  These assemblies must comply with workmanship standards IPC-A-610 Class 2, unless otherwise specified.  [AssemblyNote]  (no BOM)

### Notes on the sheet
- Variant
- Variant/Label Table
- Label Text
- You should delete the nylon screws/standoffs and/or the bumpons as needed for your design (or substitute other parts from Hardware.IntLib).  Bumpons are cheaper, but provide less clearance.
  Deleting anything else from this page may result in your EVM submission being rejected (until you add them back).
  Update the Label Text in the Label Table as needed for each Assembly Variant.
  You should delete this note too.
- 001
- LMG3650EVM-113

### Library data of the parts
!PCB = CMP-0003618-2: Manufacturer: Any; PartNumber: HVP113
H1 = HeatSink_NoPins: Heat Sink, Black Anodized, 35 x 50 mm,  20 mm high, with Push Pin and Spring; Manufacturer: Alpha Novatech; PartNumber: S05MZZ13
H2 = CMP-0080604-2: Manufacturer: Fuji Polymer Industries; PartNumber: GR80A-0H-50GY; CompType: Mechanical
LBL1 = CMP-0003625-1: Thermal Transfer Printable Labels, 0.650" W x 0.200" H - 10,000 per roll; Manufacturer: Brady; CompType: Label
LOGO1 LOGO3 = CMP-0074837-1: IEC 61010-1 Hot Surface Warning; SymbolCreator: a0412235; Lib Reference: IEC_HotSurface
LOGO2 LOGO4 = CMP-0074835-1: IEC 61010-1 High Voltage Warning; SymbolCreator: a0412235; Lib Reference: IEC_HighVoltage
Logo5 = CMP-0074844-1: SymbolCreator: a0412235
Logo6 = CMP-0074838-1: Texas Instrument Corporate Signature; SymbolCreator: a0412235; Lib Reference: TI_Logo; Library Reference: Logo
Logo7 = CMP-0074847-1: FCC_disclaimer; Library Reference: Logo
Logo8 = CMP-0074769-1
ZZ1 = CMP-0003616-3
ZZ2 = CMP-0077236-1
ZZ3 = CMP-0077237-1
ZZ4 = CMP-0077238-1

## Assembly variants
LMG3650EVM-113: not fitted CgB CgT D4 D7 D8 D9 DoffB DoffT R2 R10 RoffB RoffT RonB RonT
